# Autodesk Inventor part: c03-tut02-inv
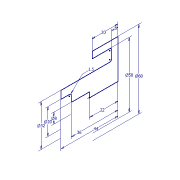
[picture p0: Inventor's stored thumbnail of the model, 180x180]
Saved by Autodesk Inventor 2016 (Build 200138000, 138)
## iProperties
Created: 2010-01
Part Number: c03-tut02-inv
Document SubType Name: Modeling
Designer: CADSoft
Density: 1 g/cm^3
Material: Generic
Appearance: Default
Author: CADSoft
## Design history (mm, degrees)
sketch "Sketch1"
  geometry: L1 (22, 0)-(22, 30); L2 (22, 30)-(2, 30); L3 (2, 30)-(2, 25); L4 (2, 25)-(15.5, 25); L5 (17, 23.5)-(17, 17.5); L6 (15.5, 16)-(-22, 16); L7 (-22, 16)-(-22, 10); L8 (-22, 10)-(-15.5, 10); L9 (-14, 8.5)-(-14, 4); L10 (-14, 4)-(0, 4); L11 (0, 4)-(0, 0); L12 (0, 0)-(22, 0); A1 r 1.5 centre (-15.5, 8.5) between (-14, 8.5) and (-15.5, 10); A2 r 1.5 centre (15.5, 23.5) between (17, 23.5) and (15.5, 25); A3 r 1.5 centre (15.5, 17.5) between (15.5, 16) and (17, 17.5); 2 further points
  constraints: 24 end point, 6 point on circle, 6 tangent, 3 centre point, 2 coincident, 2 equal radius, 2 vertical, 1 horizontal, 1 other
  dimensions: "d0" = 8 diameter of L10 L12; "d1" = 20 diameter of L8 L12; "d2" = 32 diameter of L6 L12; "d3" = 50 diameter of L4 L12; "d5" = 60 diameter of L2 L12; "d6" = 5 distance between parallel lines of L5 L1; "d7" = 20 distance of L1.end L2.end; "d8" = 22 distance of L11.end L1.start; "d9" = 36 distance between parallel lines of L9 L1; "d10" = 44 distance between parallel lines of L7 L1; "d11" = 1.5 radius of A1
